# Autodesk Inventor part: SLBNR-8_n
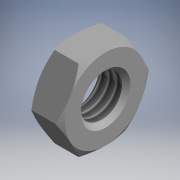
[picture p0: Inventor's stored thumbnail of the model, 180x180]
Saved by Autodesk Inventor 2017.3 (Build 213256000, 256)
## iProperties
Part Number: SLBNR-8_n
Material: Generic
Catalog Web Link: www.cadenas.de
Description: UNST_n-Stopper Bolts with Bumpers-Threaded Soft Bumpers
Vendor: MISUMI
Document SubType Name: Modeling
Designer: partserver
Manufacturer: MISUMI
Mass: 0.543312 g
Surface Area: 5.23813 cm^2
Volume: 0.543312 cm^3
Density: 1 g/cm^3
Appearance: PSOLRGB-192-192-192
Category: PARTsolutions
Company: MISUMI
Title: M8x1.25A
Author: Cadenas PARTsolutions
Comments: Stopper Bolts with Bumpers-Threaded Soft Bumpers
PSOL_IDENT_0: {$CADENAS_DATA\23d-libs\misumi\metric\15_locating_components\unst_n.prj},157 {VTYP=3D},{NB=SLBNR-8_n
PSOL_IDENT_1: },{LINA=M8x1.25A},{NN=UNST_n},{DATE=02.06.2021 05:59:50},{GEOMDATE=21.02.2011 05:03:00},{VERSION=},{
PSOL_IDENT_2: LINEID=60},{WBVAR=},{WBNUMERIC=}  {NB=SLBNR-8_n},{LINA=M8x1.25A},{KT=DUMMY},{PN=SLBNR-8},{AC=SLBNR},
PSOL_IDENT_3: {NUT=M8x1.25},{M=8},{MMIN=6.647},{B=13.0},{C=18},{MM=5.0}
NB: SLBNR-8_n
NN: UNST_n
NT: Stopper Bolts with Bumpers-Threaded Soft Bumpers
NBSYN: $PN._n
LINA: M8x1.25A
CATALOG: Misumi
PN: SLBNR-8
NUT: M8x1.25
M: 8
B: 13
C: 18
MM: 5
SUPPLIER: MISUMI
ARTICLENO: SLBNR-8_n
BOMINFO: M8x1.25A
CREATOR: CADENAS GmbH
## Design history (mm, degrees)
sketch "Sketch_1"
  geometry: L1 (2.5, 0)-(-2.5, 0); L2 (-2.5, 0)-(-2.5, 6.5); L3 (-2.5, 6.5)-(-1.057, 9); L4 (-1.057, 9)-(1.057, 9); L5 (1.057, 9)-(2.5, 6.5); L6 (2.5, 6.5)-(2.5, 0); L7 (2.5, 0)-(-2.5, 0)
  constraints: 14 end point
revolve "Revolution1" sketch "Sketch_1" stored, may be unused: angle "d0" = 360 deg
sketch "Sketch_2"
  geometry: L1 (18, 18)-(-18, 18); L2 (-18, 18)-(-18, -18); L3 (-18, -18)-(18, -18); L4 (18, -18)-(18, 18); L5 (-3.753, 6.5)-(-7.506, 0); L6 (-7.506, 0)-(-3.753, -6.5); L7 (-3.753, -6.5)-(3.753, -6.5); L8 (3.753, -6.5)-(7.506, 0); L9 (7.506, 0)-(3.753, 6.5); L10 (3.753, 6.5)-(-3.753, 6.5)
  constraints: 20 end point
extrude "Extrusion1" cut sketch "Sketch_2" stored distance "d1" = 10; taper "d2" = 0 deg
sketch "Sketch_3"
  geometry: L1 (2.5, 0)-(-2.5, 0); L2 (-2.5, 0)-(-2.5, 4); L3 (-2.5, 4)-(-1.824, 3.324); L4 (-1.824, 3.324)-(1.824, 3.324); L5 (1.824, 3.324)-(2.5, 4); L6 (2.5, 4)-(2.5, 0); L7 (2.5, 0)-(-2.5, 0)
  constraints: 14 end point
revolve "Revolution2" sketch "Sketch_3" stored, may be unused: angle "d3" = 360 deg
thread "Thread1" dims "d4" = 3.647, "d5" = 0
node "n_b_XY"
node "n_b_YZ"
node "n_b_ZX"
node "n_b_X"
node "n_b_Y"
node "n_b_Z"
node "n_b_Center"
body "Solid1"
